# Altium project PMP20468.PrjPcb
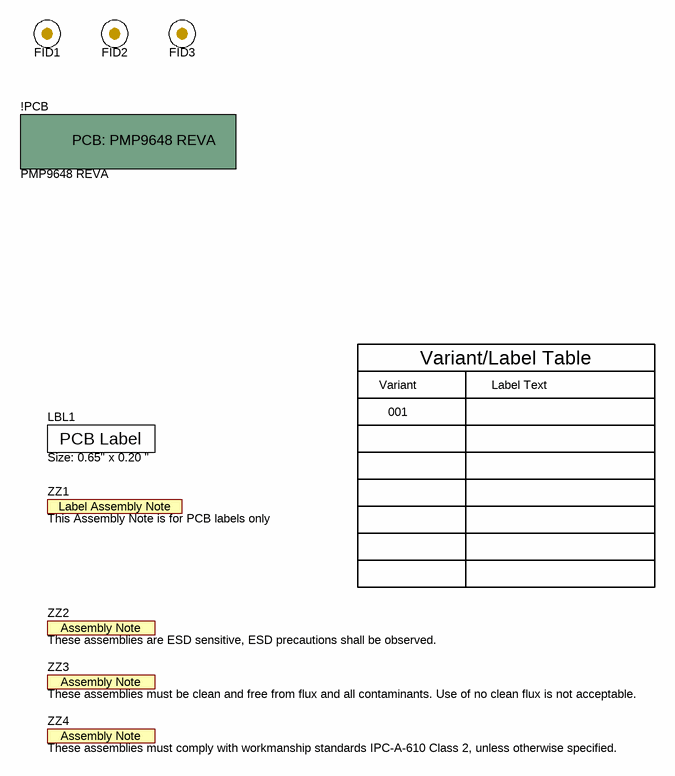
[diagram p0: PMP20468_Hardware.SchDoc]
CopyrightYear: 2016; PCB_Layout: J Betten; PRJ_Customer: Public Release; PRJ_Engineer: J Doong; PRJ_Number: PMP20468; PRJ_Title: LM5022 Isolated Flyback; SCH_Rev: A; TechSupport: http://www.ti.com/support; TID: N/A
2 sheets, 67 parts. Net scope: global (net labels, ports and power ports of the same name join across sheets).
Board file: PMP9648 REVA.PcbDoc
Sheets:
  PMP20468_Hardware.SchDoc
  PMP20468.SchDoc

## Sheet PMP20468_Hardware.SchDoc
size 431 x 279 mm; Date: Not shown in title block; ApprovedBy: Not shown in title block; CheckedBy: Not shown in title block; Author: Not shown in title block; CompanyName: Not shown in title block; Engineer: Not shown in title block; Organization: Not shown in title block; Address1: Not shown in title block; Address2: Not shown in title block; Address3: Not shown in title block; Address4: Not shown in title block; DocumentNumber: 1; Revision: Use project parameter SCH_Rev; SheetNumber: 3; SheetTotal: 3; PageSetup: Record=PageOptions¦CenterHorizontal=True¦CenterVertical=True¦PrintScale=1.00¦XCorrection=1.00¦YCorrection=1.00¦PrintKind=0¦BorderSize=5000000¦LeftOffset=0¦BottomOffset=0¦Orientation=2¦PaperLength=1000¦PaperWidth=1000¦Scale=100¦PaperSource=15¦PrintQuality=600¦MediaType=1¦DitherType=10¦PaperKind=Letter¦PrintScaleMode=1

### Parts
!PCB  PMP9648 REVA  (mechanical)
FID1  Fiducial  [Fiducial10-20]  (value not drawn)
FID2  Fiducial  [Fiducial10-20]  (value not drawn)
FID3  Fiducial  [Fiducial10-20]  (value not drawn)
LBL1  Size: 0.65" x 0.20 "  [Label_650x200]
ZZ1  This Assembly Note is for PCB labels only  [AssemblyNoteLabel]  (no BOM)
ZZ2  These assemblies are ESD sensitive, ESD precautions shall be observed.  [AssemblyNote]  (no BOM)
ZZ3  These assemblies must be clean and free from flux and all contaminants. Use of no clean flux is not acceptable.  [AssemblyNote]  (no BOM)
ZZ4  These assemblies must comply with workmanship standards IPC-A-610 Class 2, unless otherwise specified.  [AssemblyNote]  (no BOM)

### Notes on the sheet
- Variant
- Variant/Label Table
- Label Text
- 001

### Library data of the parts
!PCB = PCB_OtherProject: Manufacturer: Any; SymbolCreator: a0412235; CompType: PCB; U/M: EA
FID1-FID3 = Fiducial: Fiducial mark.  There is nothing to buy or mount.; SymbolCreator: codlsc
LBL1 = THT-14-423-10: Thermal Transfer Printable Labels, 0.650" W x 0.200" H - 10,000 per roll; Manufacturer: Brady; SymbolCreator: a0412235; CompType: Label
ZZ1 = AssemblyNoteLabel: SymbolCreator: a0412235
ZZ2-ZZ4 = AssemblyNote: SymbolCreator: codlsc

## Sheet PMP20468.SchDoc
size 431 x 279 mm; Date: Not shown in title block; ApprovedBy: Not shown in title block; CheckedBy: Not shown in title block; Author: Not shown in title block; CompanyName: Not shown in title block; Engineer: Not shown in title block; Organization: Not shown in title block; Address1: Not shown in title block; Address2: Not shown in title block; Address3: Not shown in title block; Address4: Not shown in title block; DocumentNumber: 1; Revision: Use project parameter SCH_Rev; SheetNumber: 2; SheetTotal: 3; PageSetup: Record=PageOptions¦CenterHorizontal=True¦CenterVertical=True¦PrintScale=0.59¦XCorrection=1.00¦YCorrection=1.00¦PrintKind=0¦BorderSize=5000000¦LeftOffset=0¦BottomOffset=0¦Orientation=2¦PaperLength=1000¦PaperWidth=1000¦Scale=100¦PaperSource=15¦PrintQuality=600¦MediaType=1¦DitherType=10¦PrintScaleMode=1¦PaperKind=Letter
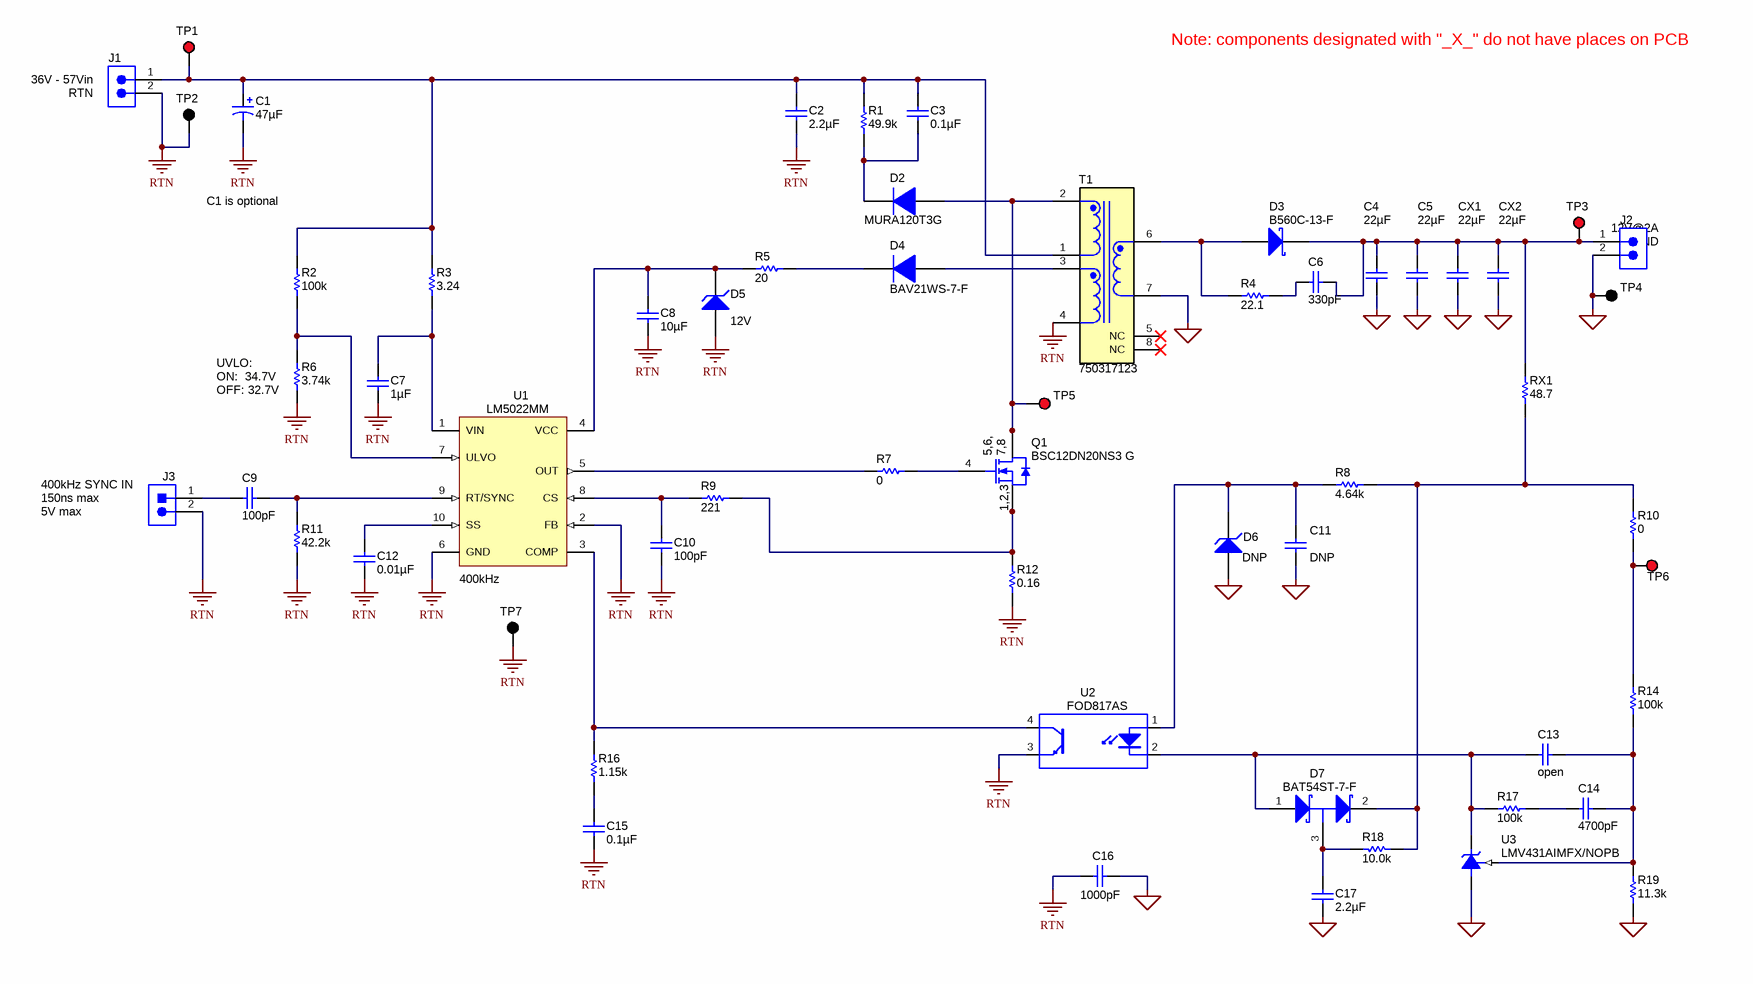
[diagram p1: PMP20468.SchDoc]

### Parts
C1  ValueDisplayed: 47µF  [SM_RADIAL_H13]  (hidden comment: EEV-FK2A470Q)
C2  ValueDisplayed: 2.2µF  [1210L]  (hidden comment: C3225X7R2A225M230AB)
C3  ValueDisplayed: 0.1µF  [0603]  (hidden comment: GRM188R72A104KA35D)
C4  ValueDisplayed: 22µF  [1210]  (hidden comment: C3225X7R1C226M250AC)
C5  ValueDisplayed: 22µF  [1210]  (hidden comment: C3225X7R1C226M250AC)
C6  ValueDisplayed: 330pF  [0805_HV]  (hidden comment: GRM2165C2A331JA01D)
C7  ValueDisplayed: 1µF  [1206]  (hidden comment: C3216X7R2A105M160AA)
C8  ValueDisplayed: 10µF  [1206]  (hidden comment: C3216X7R1C106M)
C9  ValueDisplayed: 100pF  [0603]  (hidden comment: C1608C0G1H101J)
C10  ValueDisplayed: 100pF  [0603]  (hidden comment: C1608C0G1H101J)
C11  DNP  [0603]
C12  ValueDisplayed: 0.01µF  [0603]  (hidden comment: C1608X7R1H103K)
C13  ValueDisplayed: open  [0603]
C14  ValueDisplayed: 4700pF  [0603]  (hidden comment: C1608X7R2A472K)
C15  ValueDisplayed: 0.1µF  [0603]  (hidden comment: GRM188R72A104KA35D)
C16  ValueDisplayed: 1000pF  [1210L]  (hidden comment: C1210C102KGRACTU)
C17  ValueDisplayed: 2.2µF  [0805_HV]  (hidden comment: GRM21BR61E225KA12L)
CX1  ValueDisplayed: 22µF  [1210]  (hidden comment: C3225X7R1C226M250AC)
CX2  ValueDisplayed: 22µF  [1210]  (hidden comment: C3225X7R1C226M250AC)
D2  MURA120T3G  [SMA]
D3  B560C-13-F  [SMC]
D4  BAV21WS-7-F  [SOD-323]
D5  value 12V  [SOD-123]  (hidden comment: MMSZ4699T1G)
D6  DNP  [SOD-123]
D7  BAT54ST-7-F  [SOT-523]
J1  ED555/2DS  [TERM_BLK_ED555-2DS]  (value not drawn)
J2  ED555/2DS  [TERM_BLK_ED555-2DS]  (value not drawn)
J3  PEC02SAAN  [CONN_PEC02SAAN]  (value not drawn)
Q1  BSC12DN20NS3 G  [PG-TDSON-8]
R1  value 49.9k  [1206]  (hidden comment: CRCW120649K9FKEA)
R2  value 100k  [0603]  (hidden comment: CRCW0603100KFKEA)
R3  ValueDisplayed: 3.24  [0603]  (hidden comment: CRCW06033R24FKEA)
R4  ValueDisplayed: 22.1  [0805_HV]  (hidden comment: CRCW080522R1FKEA)
R5  value 20  [1206L]  (hidden comment: CRCW120620R0JNEA)
R6  value 3.74k  [0603]  (hidden comment: CRCW06033K74FKEA)
R7  value 0  [0603]  (hidden comment: MCR03EZPJ000)
R8  ValueDisplayed: 4.64k  [0603]  (hidden comment: CRCW06034K64FKEA)
R9  value 221  [0603]  (hidden comment: CRCW0603221RFKEA)
R10  value 0  [0603]  (hidden comment: CRCW06030000Z0EA)
R11  ValueDisplayed: 42.2k  [0603]  (hidden comment: CRCW060342K2FKEA)
R12  ValueDisplayed: 0.16  [1206]  (hidden comment: RLP73K2BR16FTDF)
R14  value 100k  [0603]  (hidden comment: CRCW0603100KFKEA)
R16  ValueDisplayed: 1.15k  [0603]  (hidden comment: CRCW06031K15FKEA)
R17  value 100k  [0603]  (hidden comment: CRCW0603100KFKEA)
R18  value 10.0k  [0603]  (hidden comment: CRCW060310K0FKEA)
R19  ValueDisplayed: 11.3k  [0603]  (hidden comment: CRCW060311K3FKEA)
RX1  ValueDisplayed: 48.7  [0603]  (hidden comment: CRCW060348R7FKEA)
T1  750317123  [Wurth_750317123]
TP1  5000  [Keystone5000]  (value not drawn)
TP2  5001  [Keystone5001]  (value not drawn)
TP3  5000  [Keystone5000]  (value not drawn)
TP4  5001  [Keystone5001]  (value not drawn)
TP5  5000  [Keystone5000]  (value not drawn)
TP6  5000  [Keystone5000]  (value not drawn)
TP7  5001  [Keystone5001]  (value not drawn)
U1  LM5022MM  [MUB10A_N]
U2  FOD817AS  [N04C]
U3  LMV431AIMFX/NOPB  [MF03A_N]

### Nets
GND2: C4.2 C5.2 C11.2 C16.1 C17.2 CX1.2 CX2.2 D6.2(A) J2.2 R19.1 T1.7 TP4.1 U3.3(A)
RTN: C1.2(-) C2.2 C7.2 C8.2 C10.1 C12.2 C15.2 C16.2 D5.2(A) J1.2 J3.2 R6.1 R11.1 R12.1 T1.4 TP2.1 TP7.1 U1.2(FB) U1.6(GND) U2.3(E)
NetC1_1: C1.1(+) C2.1 C3.1 J1.1 R1.2 R2.2 R3.2 T1.1 TP1.1
NetC3_2: C3.2 D2.1(K) R1.1
NetC4_1: C4.1 C5.1 C6.1 CX1.1 CX2.1 D3.1(K) J2.1 RX1.2 TP3.1
NetC6_2: C6.2 R4.2
NetC7_1: C7.1 R3.1 U1.1(VIN)
NetC8_1: C8.1 D5.1(K) R5.2 U1.4(VCC)
NetC9_1: C9.1 J3.1
NetC9_2: C9.2 R11.2 U1.9(RT/SYNC)
NetC10_2: C10.2 R9.1 U1.8(CS)
NetC11_1: C11.1 D6.1(K) R8.1 U2.1(A)
NetC12_1: C12.1 U1.10(SS)
NetC13_1: C13.1 D7.1(A) R17.2 U2.2(K) U3.2(K)
NetC13_2: C13.2 C14.2 R14.1 R19.2 U3.1(REF)
NetC14_1: C14.1 R17.1
NetC15_1: C15.1 R16.1
NetC17_1: C17.1 D7.3(C) R18.1
NetD2_2: D2.2(A) Q1.5(D) Q1.6(D) Q1.7(D) Q1.8(D) Q1.9(D) T1.2 TP5.1
NetD3_2: D3.2(A) R4.1 T1.6
NetD4_1: D4.1(K) R5.1
NetD4_2: D4.2(A) T1.3
NetD7_2: D7.2(K) R8.2 R10.2 R18.2 RX1.1
NetQ1_1: Q1.1(S) Q1.2(S) Q1.3(S) R9.2 R12.2
NetQ1_4: Q1.4(G) R7.2
NetR2_1: R2.1 R6.2 U1.7(ULVO)
NetR7_1: R7.1 U1.5(OUT)
NetR10_1: R10.1 R14.2 TP6.1
NetR16_2: R16.2 U1.3(COMP) U2.4(C)

Not connected (* = marked no-connect by the designer): T1 5(NC)* 8(NC)*

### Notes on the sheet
- (near J1) 36V - 57Vin
- (near J1) RTN
- Note: components designated with "_X_" do not have places on PCB
- C1 is optional
- (near J2) 12V@2A
- (near J2) GND
- UVLO:
- (near R6) ON:  34.7V
- (near R6) OFF: 32.7V
- (near J3) 400kHz SYNC IN
- 150ns max
- 5V max
- (near U1) 400kHz

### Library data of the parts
C1 = EEV-FK2A470Q: CAP, AL, 47uF, 100V, +/-20%, 0.32 ohm, SMD; Manufacturer: Panasonic; Polarized: Y; CompType: Capacitor; U/M: EA; Cap_F: 0.000047; Tolerance_%: 20; VDC_V: 100; ESR_Ohm: 0.32; IRMS_A: 0.5; TaMin_C: -55; TaMax_C: 105; Cap_Case: H13
C2 = C3225X7R1C226M: CAP, CERM, 2.2uF, 100V, +/-20%, X7R, 1210; Manufacturer: TDK; Polarized: N; CompType: Capacitor; U/M: EA; Cap_F: 0.000022; Tolerance_%: 20; ESR_Ohm: 0.002; Value1: 0.002 ohm; VDC_V: 100; IRMS_A: 8.11; TaMin_C: -55; TaMax_C: 125; Cap_Case: 1210
C3 C15 = GRM188R72A104KA35D: CAP, CERM, 0.1uF, 100V, +/-10%, X7R, 0603; Manufacturer: MuRata; Polarized: N; CompType: Capacitor; U/M: EA; Cap_F: 0.0000001; Tolerance_%: 10; Value1: Unknown; VDC_V: 100; TaMin_C: -55; TaMax_C: 125
C4 C5 CX1 CX2 = C3225X7R1C226M: CAP, CERM, 22uF, 16V, +/-20%, X7R, 1210; Manufacturer: TDK; Polarized: N; CompType: Capacitor; U/M: EA; Cap_F: 0.000022; Tolerance_%: 20; ESR_Ohm: 0.002; Value1: 0.002 ohm; VDC_V: 16; IRMS_A: 8.11; TaMin_C: -55; TaMax_C: 125
C6 = GRM2165C2A331JA01D: CAP, CERM, 330 pF, 100 V, +/- 5%, C0G/NP0, 0805; Manufacturer: MuRata; Polarized: N; CompType: Capacitor; Value: 330pF; U/M: EA; Cap_F: 0.00000000033; Tolerance_%: 5; Value1: Unknown; VDC_V: 100; Value2: 100V; TaMin_C: -55; TaMax_C: 125; Cap_Case: 0805; SizeArea_mm2: 2.5; SizeAreaWB_mm2: 6.75; SizeX_mm: 2; SizeY_mm: 1.25; SizeZ_mm: 1.45; AEC Category: Q200
C7 = C3216X7R2A105M160AA: CAP, CERM, 1uF, 100V, +/-20%, X7R, 1206; Manufacturer: TDK; Polarized: N; CompType: Capacitor; U/M: EA; Cap_F: 0.000001; Tolerance_%: 20; Value1: Unknown; VDC_V: 100; TaMin_C: -55; TaMax_C: 125
C8 = C3216X7R1C106M: CAP, CERM, 10uF, 16V, +/-20%, X7R, 1206; Manufacturer: TDK; Polarized: N; CompType: Capacitor; U/M: EA; Cap_F: 0.00001; Tolerance_%: 20; ESR_Ohm: 0.0046; Value1: 0.0046 ohm; VDC_V: 16; TaMin_C: -55; TaMax_C: 125
C9 C10 = C1608C0G1H101J: CAP, CERM, 100pF, 50V, +/-5%, C0G/NP0, 0603; Manufacturer: TDK; Polarized: N; CompType: Capacitor; U/M: EA; Cap_F: 0.0000000001; Tolerance_%: 5; ESR_Ohm: 0.1679; Value1: 0.1679 ohm; VDC_V: 50; TaMin_C: -55; TaMax_C: 125
C11 = GRM188R72A104KA35D: CAP, CERM, 0.1uF, 100V, +/-10%, X7R, 0603; Manufacturer: MuRata; Polarized: N; CompType: Capacitor; ValueDisplayed: 0.1µF; U/M: EA; Cap_F: 0.0000001; Tolerance_%: 10; Value1: Unknown; VDC_V: 100; TaMin_C: -55; TaMax_C: 125
C12 = C1608X7R1H103K: CAP, CERM, 0.01uF, 50V, +/-10%, X7R, 0603; Manufacturer: TDK; Polarized: N; CompType: Capacitor; U/M: EA; Cap_F: 0.00000001; Tolerance_%: 10; ESR_Ohm: 0.0539; Value1: 0.0539 ohm; VDC_V: 50; TaMin_C: -55; TaMax_C: 125
C13 = C1608C0G1H470J: CAP, CERM, open, 0603; Polarized: N; CompType: Capacitor; U/M: EA; Cap_F: 0.000000000047; Tolerance_%: 5; ESR_Ohm: 0.22; TempCo: C0G/NP0; TaMin_C: -55; TaMax_C: 125
C14 = C1608X7R2A472K: CAP, CERM, 4700pF, 100V, +/-10%, X7R, 0603; Manufacturer: TDK; Polarized: N; CompType: Capacitor; U/M: EA; Cap_F: 0.0000000047; Tolerance_%: 10; ESR_Ohm: 0.1099; Value1: 0.1099 ohm; VDC_V: 100; TaMin_C: -55; TaMax_C: 125
C16 = C1210C102KGRACTU: CAP, CERM, 1000pF, 2000V, +/-10%, X7R, 1210; Manufacturer: Kemet; Polarized: N; CompType: Capacitor; U/M: EA; Cap_F: 0.000000001; Tolerance_%: 10; Value1: Unknown; VDC_V: 2000; TaMin_C: -55; TaMax_C: 125; Cap_Case: 1210
C17 = GRM21BR61E225KA12L: CAP, CERM, 2.2 µF, 25 V, +/- 10%, X5R, 0805; Manufacturer: MuRata; Actual Manufacturer: Wurth Electronics Inc; Actual PartNumber: 885012107016; Polarized: N; CompType: Capacitor; Value: 2.2uF; U/M: EA; Cap_F: 0.0000022; Tolerance_%: 10; ESR_ohm: 0.008; Value1: 0.008 ohm; VDC_V: 25; Value2: 25V; TaMin_C: -55; TaMax_C: 85; Cap_Case: 0805; SizeArea_mm2: 2.5; SizeAreaWB_mm2: 6.75; SizeX_mm: 2; SizeY_mm: 1.25; SizeZ_mm: 1.45; AEC Category: Q200; Actual Tolerance_%: 20
D2 = MURA120T3G: Diode, Ultrafast, 200V, 1A, SMA; Manufacturer: ON Semiconductor; U/M: EA; Vf_V: 0.0875; Value2: 0.0875V; Io_A: 1; Vr_V: 200; TJmax_C: 175
D3 = B560C-13-F: Diode, Schottky, 60 V, 5 A, SMC; Manufacturer: Diodes Inc.; U/M: EA; Vf_V: 0.7; Value: 60V; Value1: 5A; Value2: 0.7V; Io_A: 5; Vr_V: 60; TJmax_C: 125; RJC_CperW: 10; SizeAreaWB_mm2: 83.2686; SizeArea_mm2: 50.5686; SizeX_mm: 8.13; SizeY_mm: 6.22; SizeZ_mm: 2.6; AEC Category: Q101
D4 = BAV21WS-7-F: Diode, Switching, 200 V, 0.2 A, AEC-Q101, SOD-323; Manufacturer: Diodes Inc.; U/M: EA; Vf_V: 1.25; Value: 200V; Value1: 0.2A; Value2: 1.25V; Io_A: 0.25; Vr_V: 250; TJmax_C: 150; SizeAreaWB_mm2: 8.695; SizeArea_mm2: 3.645; SizeX_mm: 2.7; SizeY_mm: 1.35; SizeZ_mm: 1; AEC Category: Q101; AEC Qualified: Y
D5 = MMSZ4699T1G: Diode, Zener, 12 V, 500 mW, SOD-123; Manufacturer: ON Semiconductor; Alternate Manufacturer: Central Semiconductor Corp; Alternate PartNumber: CMHZ4699TR; SymbolCreator: a0412235; U/M: EA; Power_W: 0.5; Vz_V: 12; Value1: 0.5W; RJA_CperW: 340; SizeAreaWB_mm2: 13.095; SizeArea_mm2: 6.545; SizeX_mm: 3.85; SizeY_mm: 1.7; SizeZ_mm: 1.35; AEC Category: Q101
D6 = MMSZ5236B-7-F: Diode, Zener, 7.5V, 500mW, SOD-123; Manufacturer: Diodes Inc.; SymbolCreator: a0412235; U/M: EA; Power_W: 0.5; Vz_V: 7.5; Value1: 0.5W; RJA_CperW: 350
D7 = BAT54ST-7-F: Diode, Schottky, 30V, 0.2A, SOT-523; Manufacturer: Diodes Inc.; U/M: EA; Vf_V: 1; Value2: 1V; Io_A: 0.2; Vr_V: 30; TJmax_C: 125
J1 J2 = ED555/2DS: Terminal Block, 6A, 3.5mm Pitch, 2-Pos, TH; Manufacturer: On-Shore Technology, Inc.; SymbolCreator: a0412235; CompType: Connector; U/M: EA
J3 = PEC02SAAN: Header, 100mil, 2x1, Tin plated, TH; Manufacturer: Sullins Connector Solutions; SymbolCreator: a0412235; U/M: EA
Q1 = BSC12DN20NS3 G: MOSFET, N-CH, 200 V, 11.3 A, PG-TDSON-8; Manufacturer: Infineon Technologies; Alternate Manufacturer: None; U/M: EA; ChType: N; Value: 200V; VdsMax_V: 200; Value1: ? ohm; Value2: 6.5 nC; QgTyp_nC: 6.5; Vgs_V: 20; IdsMax_A: 11.3; SizeAreaWB_mm2: 55.131; SizeArea_mm2: 29.351; SizeX_mm: 5.99; SizeY_mm: 4.9; SizeZ_mm: 1.12; AEC Category: Q101
R1 = CRCW120649K9FKEA: RES, 49.9k ohm, 1%, 0.25W, 1206; Manufacturer: Vishay-Dale; CompType: Resistor; Res_ohm: 49900; Value_Code: 49k9; Tolerance_%: 1; Power_W: 0.25; VDC_V: 200; TempCo: 100 ppm/C; EIA_Code: E96; U/M: EA
R2 R14 R17 = CRCW0603100KFKEA: RES, 100k ohm, 1%, 0.1W, 0603; Manufacturer: Vishay-Dale; CompType: Resistor; Res_ohm: 100000; Tolerance_%: 1; Power_W: 0.1; VDC_V: 75; TempCo: 100 ppm/C; EIA_Code: E96; U/M: EA
R3 = CRCW06033R24FKEA: RES, 3.24, 1%, 0.1 W, 0603; Manufacturer: Vishay-Dale; CompType: Resistor; Value: 3.24; Value_Code: 3R24; Tolerance_%: 1; Power_W: 0.1; Value2: 0.1W; VDC_V: 75; TempCo: 100 ppm/C; SizeArea_mm2: 1.28; SizeX_mm: 1.6; SizeY_mm: 0.8; EIA_Code: E96; U/M: EA; AEC Category: Q200
R4 = CRCW080522R1FKEA: RES, 22.1, 1%, 0.125 W, 0805; Manufacturer: Vishay-Dale; CompType: Resistor; Value: 22.1; Value_Code: 22R1; Tolerance_%: 1; Power_W: 0.125; Value2: 0.125W; VDC_V: 150; TempCo: 100 ppm/C; SizeArea_mm2: 2.5; SizeX_mm: 2; SizeY_mm: 1.25; SizeZ_mm: 1.45; EIA_Code: E96; U/M: EA; AEC Category: Q200
R5 = CRCW120620R0JNEA: RES, 20 ohm, 5%, 0.25W, 1206; Manufacturer: Vishay-Dale; CompType: Resistor; Value_Code: 20R0; Tolerance_%: 5; Power_W: 0.25; VDC_V: 200; TempCo: 200 ppm/C; EIA_Code: E24; U/M: EA
R6 = CRCW06033K74FKEA: RES, 3.74k ohm, 1%, 0.1W, 0603; Manufacturer: Vishay-Dale; CompType: Resistor; Res_ohm: 3740; Value_Code: 3k74; Tolerance_%: 1; Power_W: 0.1; VDC_V: 75; TempCo: 100 ppm/C; EIA_Code: E96; U/M: EA
R7 = MCR03EZPJ000: RES, 0 ohm, 5%, 0.1W, 0603; Manufacturer: Rohm; CompType: Resistor; Value_Code: 0000; Tolerance_%: 5; Power_W: 0.1; VDC_V: 50; TempCo: 400 ppm/C; EIA_Code: E24; U/M: EA
R8 = CRCW06034K64FKEA: RES, 4.64 k, 1%, 0.1 W, 0603; Manufacturer: Vishay-Dale; CompType: Resistor; Value: 4.64k; Res_ohm: 4640; Value_Code: 4k64; Tolerance_%: 1; Power_W: 0.1; Value2: 0.1W; VDC_V: 75; TempCo: 100 ppm/C; SizeArea_mm2: 1.28; SizeX_mm: 1.6; SizeY_mm: 0.8; EIA_Code: E96; U/M: EA; AEC Category: Q200
R9 = CRCW0603221RFKEA: RES, 221 ohm, 1%, 0.1W, 0603; Manufacturer: Vishay-Dale; CompType: Resistor; Value_Code: 221R; Tolerance_%: 1; Power_W: 0.1; VDC_V: 75; TempCo: 100 ppm/C; EIA_Code: E96; U/M: EA
R10 = CRCW06030000Z0EA: RES, 0 ohm, 5%, 0.1W, 0603; Manufacturer: Vishay-Dale; CompType: Resistor; Value_Code: 0000; Tolerance_%: 5; Power_W: 0.1; VDC_V: 75; TempCo: 200 ppm/C; EIA_Code: E24; U/M: EA
R11 = CRCW060342K2FKEA: RES, 42.2 k, 1%, 0.1 W, 0603; Manufacturer: Vishay-Dale; CompType: Resistor; Value: 42.2k; Res_ohm: 42200; Value_Code: 42k2; Tolerance_%: 1; Power_W: 0.1; Value2: 0.1W; VDC_V: 75; TempCo: 100 ppm/C; SizeArea_mm2: 1.28; SizeX_mm: 1.6; SizeY_mm: 0.8; EIA_Code: E96; U/M: EA; AEC Category: Q200
R12 = RLP73K2BR16FTDF: RES, 0.16, 1%, 0.5 W, 1206; Manufacturer: TE Connectivity; CompType: Resistor; Value: 0.16; Value_Code: R160; Tolerance_%: 1; Power_W: 0.5; Value2: 0.5W; TempCo: 200 ppm/C; SizeArea_mm2: 5.12; SizeX_mm: 3.2; SizeY_mm: 1.6; SizeZ_mm: 1.35; EIA_Code: E96; U/M: EA; AEC Category: Q200; AEC Qualified: N
R16 = CRCW06031K15FKEA: RES, 1.15 k, 1%, 0.1 W, 0603; Manufacturer: Vishay-Dale; CompType: Resistor; Value: 1.15k; Res_ohm: 1150; Value_Code: 1k15; Tolerance_%: 1; Power_W: 0.1; Value2: 0.1W; VDC_V: 75; TempCo: 100 ppm/C; SizeArea_mm2: 1.28; SizeX_mm: 1.6; SizeY_mm: 0.8; EIA_Code: E96; U/M: EA; AEC Category: Q200
R18 = CRCW060310K0FKEA: RES, 10.0k ohm, 1%, 0.1W, 0603; Manufacturer: Vishay-Dale; CompType: Resistor; Res_ohm: 10000; Value_Code: 10k0; Tolerance_%: 1; Power_W: 0.1; VDC_V: 75; TempCo: 100 ppm/C; EIA_Code: E96; U/M: EA
R19 = CRCW060311K3FKEA: RES, 11.3 k, 1%, 0.1 W, 0603; Manufacturer: Vishay-Dale; CompType: Resistor; Value: 11.3k; Res_ohm: 11300; Value_Code: 11k3; Tolerance_%: 1; Power_W: 0.1; Value2: 0.1W; VDC_V: 75; TempCo: 100 ppm/C; SizeArea_mm2: 1.28; SizeX_mm: 1.6; SizeY_mm: 0.8; EIA_Code: E96; U/M: EA; AEC Category: Q200
RX1 = CRCW060348R7FKEA: RES, 48.7, 1%, 0.1 W, 0603; Manufacturer: Vishay-Dale; CompType: Resistor; Value: 48.7; Value_Code: 48R7; Tolerance_%: 1; Power_W: 0.1; Value2: 0.1W; VDC_V: 75; TempCo: 100 ppm/C; SizeArea_mm2: 1.28; SizeX_mm: 1.6; SizeY_mm: 0.8; EIA_Code: E96; U/M: EA; AEC Category: Q200
T1 = CMP-0081509-1: Transformer, 82 uH, SMD; Manufacturer: Wurth Elektronik; SizeAreaWB_mm2: 526.1488; SizeArea_mm2: 438.3288; AEC Qualified: N; Lp: 82; AEC Category: Q200; Value: 82uH; SizeZ_mm: 13.2; Ind_H: 82µH; SizeY_mm: 20.07; Ns1toNp: 0.4; LeakageInd_H: 600nH; Rsec1_ohm: 0.016; DCR_ohm: 0.088; SizeX_mm: 21.84
TP1 TP3 TP5 TP6 = 5000: Test Point, TH, Miniature, Red; Manufacturer: Keystone; CompType: Test Point Loop; U/M: EA
TP2 TP4 TP7 = 5001: Test Point, TH, Miniature, Black; Manufacturer: Keystone; CompType: Test Point Loop; U/M: EA
U1 = LM5022MM: 60V Low Side Controller for Boost and SEPIC, 10-pin MSOP; Manufacturer: Texas Instruments; PackageTopMarking: ZXTT*5022; PowerWise: Y; CompType: Switcher
U2 = FOD817DS: Optocoupler, 5kV RMS, 80% - 160%, SMT; Manufacturer: Fairchild Semiconductor; U/M: EA
U3 = LMV431AIMFX/NOPB: Low-Voltage (1.24V) Adjustable Precision Shunt Regulators, 3-pin SOT-23, Pb-Free; Manufacturer: Texas Instruments; PackageTopMarking: RLA*XTT; PowerWise: N; CompType: MiscPower

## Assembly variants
001: not fitted C11 D6 FID1 FID2 FID3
